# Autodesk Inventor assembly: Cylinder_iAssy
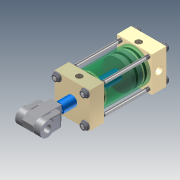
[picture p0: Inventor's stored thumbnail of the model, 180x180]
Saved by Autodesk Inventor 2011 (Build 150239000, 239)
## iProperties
Created: 2010-02
Part Number: Cylinder_iAssy
Document SubType Name: Assembly
Designer: PN
Author: PN
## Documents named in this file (17)
- C:\Temp\Cylinder_iAssy.iam
- C:\Temp\Cylinder Head Cover_Front.ipt
- C:\Temp\Cylinder Head Cover_Back.ipt
- C:\Temp\Cylinder Body\TU-004-01.ipt
- C:\_iAssembly SB Components\Cylinder Body.ipt
- C:\Temp\Gland O-ring.ipt
- C:\Temp\Piston Rod\TU-006-01.ipt
- C:\_iAssembly SB Components\Piston Rod.ipt
- C:\Temp\Piston.ipt
- C:\Temp\AS 1969 - M8(1).ipt
- C:\Temp\ANSI B18.2.4.2M - M8x1.25 - 13.ipt
- C:\Temp\Piston O-ring.ipt
- C:\Temp\M5 Threaded Rod\TU-003-01.ipt
- C:\_iAssembly SB Components\M5 Threaded Rod.ipt
- C:\Temp\ANSI B18.2.4.4M - M5 x 0.8.ipt
- C:\Temp\Rod Clevis.ipt
- C:\Temp\Rod Eye.ipt
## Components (24 placed, 13 different names)
1. Cylinder Head Cover_Front:1 — Angle:1, Insert:1, Mate:5, Mate:8, Flush:1, Insert:6, Mate:11, Mate:12, Angle:2, Angle:3
2. Cylinder Head Cover_Back:1 — Angle:1, Insert:2, Insert:7, Mate:13, Mate:14, Stroke Limit
3. TU-004-01:1 — Insert:1, Insert:2
4. TU-006-01:1 — Mate:5, Insert:8, Insert:11, Insert:12
5. Piston:1 — Insert:8, Mate:9, Mate:10, Insert:9, Stroke Limit
6. Piston O-ring:1 — Mate:9, Mate:10
7. Gland O-ring:1 — Mate:11, Mate:12
8. Gland O-ring:2 — Mate:13, Mate:14
9. AS 1969 (External Tooth Lock Washer Type A) M8:1 — Insert:9, Insert:10
10. ANSI B18.2.4.2M M8x1.25:1 — Insert:10
11. Rod Clevis:1 — Insert:11, Angle:2
12. Rod Eye:1 — Insert:12, Angle:3
13. TU-003-01:1 — Mate:8, Flush:1
14. Metric Hex Flange Nuts - Metric M5 x 0.8:1 — Insert:6
15. Metric Hex Flange Nuts - Metric M5 x 0.8:2 — Insert:7
16. TU-003-01:2
17. Metric Hex Flange Nuts - Metric M5 x 0.8:3
18. Metric Hex Flange Nuts - Metric M5 x 0.8:4
19. TU-003-01:3
20. Metric Hex Flange Nuts - Metric M5 x 0.8:5
21. Metric Hex Flange Nuts - Metric M5 x 0.8:6
22. TU-003-01:4
23. Metric Hex Flange Nuts - Metric M5 x 0.8:7
24. Metric Hex Flange Nuts - Metric M5 x 0.8:8
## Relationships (22: Insert 9, Mate 9, Angle 3, Flush 1)
- Angle:1: Cylinder Head Cover_Front:1 ↔ Cylinder Head Cover_Back:1
- Insert:1: Cylinder Head Cover_Front:1 ↔ TU-004-01:1
- Insert:2: Cylinder Head Cover_Back:1 ↔ TU-004-01:1
- Mate:5: Cylinder Head Cover_Front:1 ↔ TU-006-01:1
- Mate:8: Cylinder Head Cover_Front:1 ↔ TU-003-01:1
- Flush:1: Cylinder Head Cover_Front:1 ↔ TU-003-01:1
- Insert:6: Cylinder Head Cover_Front:1 ↔ Metric Hex Flange Nuts - Metric M5 x 0.8:1
- Insert:7: Cylinder Head Cover_Back:1 ↔ Metric Hex Flange Nuts - Metric M5 x 0.8:2
- Insert:8: TU-006-01:1 ↔ Piston:1
- Mate:9: Piston:1 ↔ Piston O-ring:1
- Mate:10: Piston:1 ↔ Piston O-ring:1
- Mate:11: Cylinder Head Cover_Front:1 ↔ Gland O-ring:1
- Mate:12: Cylinder Head Cover_Front:1 ↔ Gland O-ring:1
- Mate:13: Cylinder Head Cover_Back:1 ↔ Gland O-ring:2
- Mate:14: Cylinder Head Cover_Back:1 ↔ Gland O-ring:2
- Insert:9: Piston:1 ↔ AS 1969 (External Tooth Lock Washer Type A) M8:1
- Insert:10: AS 1969 (External Tooth Lock Washer Type A) M8:1 ↔ ANSI B18.2.4.2M M8x1.25:1
- Insert:11: TU-006-01:1 ↔ Rod Clevis:1
- Angle:2: Cylinder Head Cover_Front:1 ↔ Rod Clevis:1
- Insert:12: TU-006-01:1 ↔ Rod Eye:1
- Angle:3: Cylinder Head Cover_Front:1 ↔ Rod Eye:1
- Stroke Limit [Mate]: Cylinder Head Cover_Back:1 ↔ Piston:1
## Named parameters: Stroke = 0, Maximum = 35 mm, Minimum = 0
